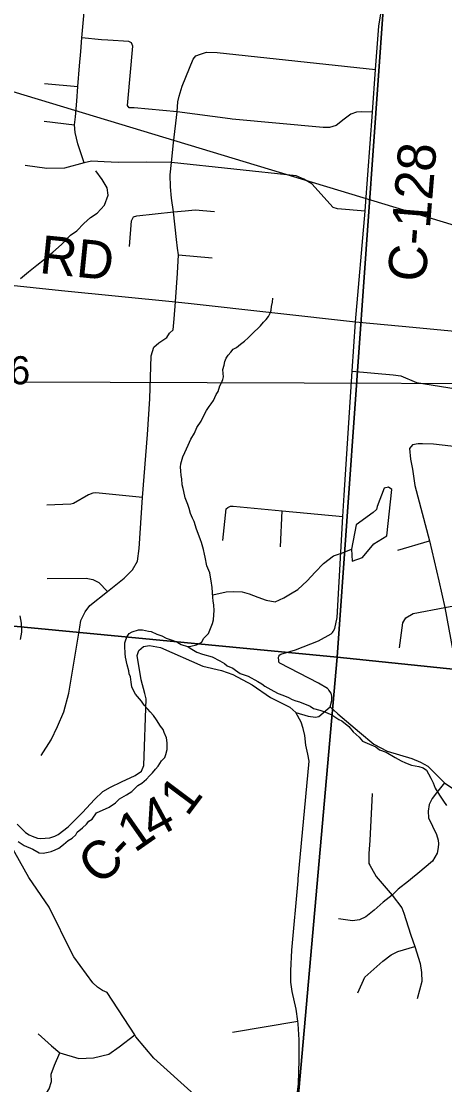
# Model space of a CAD drawing. Extents: x 0 to 43.4, y -8.1 to 22.
# Drawn here: x 5.419 to 6.05, y 17.842 to 19.427 of the extents above; entities that cross this region are included whole.
import ezdxf

# ---------------------------------------------------------------- set-up
doc = ezdxf.new("R2010")
doc.units = 0
for name, color, linetype in [('GM_X_Corporation', 7, 'Continuous'), ('GM_X_County_Road', 7, 'Continuous'), ('GM_X_County_Road_Text', 7, 'Continuous'), ('GM_X_Minor_Lake', 7, 'Continuous'), ('GM_X_Minor_River', 7, 'Continuous'), ('GM_X_Section_Text', 7, 'Continuous'), ('GM_X_Township_Road', 7, 'Continuous'), ('SH_Text', 7, 'Continuous')]:
    doc.layers.add(name, color=color, linetype=linetype)

msp = doc.modelspace()

# ---------------------------------------------------------------- linework, layer by layer
at = {"layer": 'GM_X_Corporation'}
for points in [[(5.9616, 19.4927), (5.8893, 18.4791), (4.8473, 18.579), (4.9462, 19.5972)], [(5.9616, 19.4927), (6.9413, 19.3833), (6.8431, 18.3799), (5.8893, 18.4791)], [(4.8473, 18.579), (5.8893, 18.4791), (5.7989, 17.456), (4.7377, 17.6242)], [(6.8431, 18.3799), (6.7271, 17.3517), (5.7989, 17.456), (5.8893, 18.4791)]]:
    msp.add_lwpolyline(points, close=True, dxfattribs=at)
at = {"layer": 'GM_X_County_Road'}
for p, q in [((5.9168, 18.9788), (5.9863, 18.9721)), ((5.9863, 18.9721), (6.2648, 18.9452))]:
    msp.add_line(p, q, dxfattribs=at)
for points in [[(5.9168, 18.9788), (5.9313, 19.1438), (5.9319, 19.1508), (5.942, 19.2909), (5.9466, 19.3546), (5.9513, 19.4191), (5.9555, 19.4438), (5.9566, 19.4892), (5.9673, 19.632), (5.979, 19.7684), (6.0003, 19.9928)], [(4.8872, 19.0868), (4.9964, 19.0755), (5.1827, 19.0567), (5.4785, 19.0255), (5.6484, 19.0084), (5.672, 19.006), (5.9168, 18.9788)], [(5.8839, 18.5182), (5.8859, 18.5217), (5.8895, 18.5379), (5.8981, 18.6884), (5.9, 18.7206), (5.912, 18.9052), (5.9168, 18.9788)], [(5.8029, 18.4807), (5.8032, 18.4817), (5.8054, 18.4832), (5.8273, 18.4901), (5.8618, 18.5034), (5.8807, 18.5135), (5.8824, 18.5155), (5.8834, 18.5173), (5.8839, 18.5182)], [(5.4127, 18.2303), (5.4249, 18.2175), (5.4307, 18.214), (5.435, 18.212), (5.4428, 18.2091), (5.4473, 18.2086), (5.4613, 18.2098), (5.4688, 18.2123), (5.4736, 18.2147), (5.4888, 18.226), (5.5099, 18.2473), (5.528, 18.2669), (5.5402, 18.279), (5.5518, 18.2851), (5.5683, 18.2933), (5.5883, 18.3025), (5.598, 18.3091), (5.6013, 18.3173), (5.605, 18.4167), (5.6026, 18.4248), (5.5975, 18.4451), (5.5912, 18.4814), (5.5941, 18.4889), (5.6007, 18.4947), (5.6098, 18.4963), (5.6264, 18.4932), (5.6892, 18.4657), (5.7171, 18.4591), (5.7339, 18.4532), (5.7626, 18.4375), (5.79, 18.4188), (5.8188, 18.4045), (5.828, 18.3963)], [(5.879, 18.4051), (5.8817, 18.4144), (5.8815, 18.4206), (5.8803, 18.4254), (5.8772, 18.43), (5.8767, 18.4307), (5.8752, 18.4322), (5.8616, 18.4404), (5.8042, 18.47), (5.8026, 18.4715), (5.8024, 18.4734), (5.8022, 18.4788), (5.8026, 18.4797), (5.8029, 18.4807)], [(5.828, 18.3963), (5.846, 18.3911), (5.857, 18.3896), (5.862, 18.3907), (5.879, 18.4051)], [(5.879, 18.4051), (5.8905, 18.3946), (5.9226, 18.367), (5.9442, 18.3493), (5.9637, 18.3387), (6.0009, 18.3279), (6.0136, 18.3227), (6.0245, 18.3163), (6.036, 18.305), (6.0493, 18.2915), (6.0768, 18.2732), (6.0947, 18.2642), (6.1384, 18.2479), (6.1507, 18.2449), (6.1624, 18.2455), (6.1754, 18.2495), (6.1913, 18.2615), (6.2051, 18.2755), (6.2269, 18.3063), (6.2439, 18.3223), (6.2453, 18.3236), (6.2495, 18.3271)], [(5.8315, 18.1487), (5.8476, 18.3242), (5.8457, 18.3345), (5.8427, 18.3476), (5.8413, 18.362), (5.839, 18.3727), (5.8359, 18.382), (5.828, 18.3963)], [(5.4947, 18.0367), (5.4604, 18.1066), (5.4302, 18.1506), (5.3905, 18.2206)], [(5.7951, 17.4607), (5.8068, 17.5856), (5.8243, 17.7859), (5.8319, 17.8427), (5.8327, 17.8791), (5.8329, 17.9087), (5.8314, 17.9327), (5.8309, 17.9364), (5.8283, 17.9545), (5.8224, 17.9809), (5.8205, 17.9946), (5.8203, 18.0113), (5.8217, 18.0424), (5.8312, 18.1458), (5.8315, 18.1487)], [(5.8243, 17.7859), (5.734, 17.7824), (5.7265, 17.7845), (5.7175, 17.7897), (5.6762, 17.8272), (5.6163, 17.8815), (5.5896, 17.9131), (5.5878, 17.916), (5.5467, 17.9791), (5.5399, 17.982), (5.5322, 17.9872), (5.5252, 17.9938), (5.4969, 18.0324), (5.4947, 18.0367)]]:
    msp.add_lwpolyline(points, dxfattribs=at)
at = {"layer": 'GM_X_Minor_Lake'}
for points in [[(5.9274, 18.6274), (5.9439, 18.6479), (5.9636, 18.6596), (5.9711, 18.7289), (5.9659, 18.7325), (5.9594, 18.7307), (5.9492, 18.7036), (5.9479, 18.6991), (5.9432, 18.6947), (5.9176, 18.676), (5.9106, 18.6399)], [(5.9106, 18.6399), (5.9117, 18.6222), (5.9274, 18.6274)]]:
    msp.add_lwpolyline(points, dxfattribs=at)
at = {"layer": 'GM_X_Minor_River'}
for points in [[(5.4175, 19.0433), (5.4295, 19.0533), (5.442, 19.0632), (5.4533, 19.0723), (5.4657, 19.0823), (5.4786, 19.0941), (5.4919, 19.1077), (5.5016, 19.1143), (5.5121, 19.125), (5.5219, 19.1343), (5.5316, 19.1408), (5.5429, 19.1527), (5.5483, 19.1673), (5.5467, 19.1784), (5.5395, 19.1908), (5.5296, 19.2036)], [(5.6667, 18.7067), (5.6629, 18.7163), (5.6609, 18.7259), (5.6599, 18.7305), (5.6586, 18.7358), (5.6578, 18.7446), (5.6568, 18.7496), (5.6563, 18.7564), (5.6561, 18.7622), (5.6566, 18.7671), (5.6597, 18.7776), (5.6622, 18.784), (5.6675, 18.7948), (5.6712, 18.8038), (5.6768, 18.8127), (5.6805, 18.8214), (5.6869, 18.8306), (5.6906, 18.8393), (5.6947, 18.8463), (5.6987, 18.8523), (5.7019, 18.8567), (5.7051, 18.8616), (5.7092, 18.8705), (5.712, 18.875), (5.7146, 18.8833), (5.717, 18.8878), (5.7191, 18.8926), (5.72, 18.8968), (5.7194, 18.9017), (5.7192, 18.9078), (5.721, 18.9142), (5.7219, 18.9195), (5.724, 18.9244), (5.7268, 18.9292), (5.7311, 18.9333), (5.7347, 18.9377), (5.7393, 18.9406), (5.7452, 18.9453), (5.7514, 18.9497), (5.7569, 18.9548), (5.762, 18.9599), (5.7663, 18.9643), (5.7714, 18.9687), (5.7754, 18.9728), (5.7797, 18.978), (5.7837, 18.982), (5.7869, 18.9864), (5.7897, 18.9917), (5.791, 18.9962), (5.7915, 19.0015), (5.7929, 19.0079), (5.7935, 19.014)], [(5.4586, 18.1882), (5.4632, 18.1892), (5.4693, 18.1916), (5.4747, 18.1945), (5.4818, 18.1999), (5.4888, 18.2058), (5.4946, 18.2094), (5.5001, 18.2141), (5.5021, 18.2182), (5.51, 18.2248), (5.5158, 18.2303), (5.5194, 18.2344), (5.5244, 18.2376), (5.5308, 18.2469), (5.5497, 18.2553), (5.5591, 18.2619), (5.565, 18.2677), (5.5754, 18.2738), (5.5836, 18.2789), (5.5879, 18.2833), (5.5926, 18.2877), (5.5984, 18.2913), (5.6055, 18.2971), (5.6098, 18.3019), (5.6145, 18.3067), (5.6185, 18.3119), (5.6228, 18.3163), (5.6277, 18.3245), (5.6324, 18.3293), (5.6341, 18.3341), (5.6359, 18.3413), (5.6362, 18.3512), (5.6353, 18.3588), (5.6318, 18.3665), (5.63, 18.3712), (5.626, 18.3762), (5.6203, 18.3856), (5.6156, 18.3918), (5.6108, 18.3973), (5.6072, 18.4016), (5.6017, 18.4075), (5.5981, 18.4133), (5.589, 18.4239), (5.5865, 18.4285), (5.5836, 18.4347), (5.5824, 18.4416), (5.5815, 18.4496), (5.5794, 18.4539), (5.5792, 18.4588), (5.5764, 18.4677), (5.5742, 18.4791), (5.5736, 18.4845), (5.5732, 18.4951), (5.573, 18.5001), (5.5743, 18.5046), (5.5764, 18.5095), (5.5796, 18.5143), (5.5842, 18.5168), (5.5934, 18.5199), (5.5995, 18.5197), (5.6082, 18.5179), (5.6123, 18.5174), (5.6209, 18.5133), (5.628, 18.5107), (5.6344, 18.5075), (5.6434, 18.5045), (5.6475, 18.5028), (5.652, 18.5008), (5.6568, 18.4979), (5.6662, 18.4946), (5.6716, 18.4955), (5.68, 18.4971), (5.6877, 18.5011), (5.6902, 18.5067), (5.6976, 18.514), (5.7018, 18.5241), (5.7038, 18.529), (5.7052, 18.5347), (5.7058, 18.5422), (5.706, 18.5487), (5.7055, 18.5563), (5.7046, 18.5628), (5.7044, 18.5678), (5.7039, 18.5754), (5.7031, 18.583), (5.7015, 18.5929), (5.7009, 18.5983), (5.6996, 18.6044), (5.6954, 18.6152), (5.6928, 18.6282), (5.6915, 18.6324), (5.6902, 18.6393), (5.6871, 18.6497), (5.6858, 18.6539), (5.684, 18.6593), (5.6799, 18.6697), (5.6761, 18.6809), (5.674, 18.6863), (5.6708, 18.6932), (5.6688, 18.7005), (5.6667, 18.7067)], [(5.7041, 18.572), (5.7241, 18.5761), (5.7352, 18.5769), (5.7477, 18.5761), (5.7582, 18.5732), (5.7714, 18.5686), (5.7838, 18.5641), (5.797, 18.5614), (5.8101, 18.5675), (5.8198, 18.5733), (5.8306, 18.5799), (5.8447, 18.5928), (5.8568, 18.6057), (5.8689, 18.6183), (5.8841, 18.63), (5.8975, 18.6346), (5.9106, 18.6399)], [(5.4175, 18.5054), (5.4193, 18.5163), (5.419, 18.5296), (5.417, 18.5407)], [(5.667, 18.4947), (5.6703, 18.4925), (5.6804, 18.4865), (5.689, 18.4832), (5.7033, 18.4792), (5.7145, 18.4735), (5.7215, 18.4695), (5.7256, 18.4659), (5.7338, 18.4626), (5.7379, 18.4594), (5.7449, 18.4546), (5.7569, 18.4504), (5.7711, 18.4427), (5.7774, 18.439), (5.7815, 18.4359), (5.7949, 18.4285), (5.8016, 18.4249), (5.8087, 18.4224), (5.817, 18.4187), (5.8222, 18.4158), (5.8278, 18.4137), (5.8331, 18.4124), (5.8492, 18.4061), (5.854, 18.4026), (5.8638, 18.3999), (5.8698, 18.3982), (5.8814, 18.3929), (5.8918, 18.386), (5.8963, 18.384), (5.907, 18.3756), (5.9135, 18.3678), (5.922, 18.3599), (5.9271, 18.3536), (5.9376, 18.3495), (5.9469, 18.3454), (5.9525, 18.341), (5.9626, 18.3376), (5.976, 18.3295), (5.9805, 18.3271), (5.9846, 18.3247), (5.9913, 18.3214), (6.0003, 18.318), (6.0112, 18.3158), (6.0176, 18.314), (6.0224, 18.3104), (6.0257, 18.305), (6.0288, 18.2984), (6.0324, 18.2915), (6.0355, 18.2838), (6.042, 18.2733), (6.0478, 18.2643), (6.0525, 18.2581)], [(5.4139, 18.2042), (5.4232, 18.1985), (5.436, 18.1928), (5.4456, 18.1875), (5.4513, 18.1869), (5.4586, 18.1882)]]:
    msp.add_lwpolyline(points, dxfattribs=at)
at = {"layer": 'GM_X_Township_Road'}
for p, q in [((5.5381, 19.3991), (5.509, 19.4017)), ((5.4534, 19.334), (5.5028, 19.3295)), ((5.4528, 19.2777), (5.4981, 19.2723)), ((5.6529, 19.0787), (5.7034, 19.0741)), ((5.805, 18.6432), (5.8075, 18.697)), ((5.9796, 18.6383), (6.0271, 18.6522)), ((5.7336, 17.9203), (5.8309, 17.9364))]:
    msp.add_line(p, q, dxfattribs=at)
for points in [[(5.5057, 19.3601), (5.5077, 19.3816), (5.509, 19.4017), (5.5137, 19.4564), (5.5175, 19.4906), (5.5167, 19.5074), (5.5154, 19.5189), (5.5112, 19.5354)], [(5.7301, 19.281), (5.6509, 19.2915), (5.5871, 19.2977), (5.5794, 19.2977), (5.5768, 19.3009), (5.5776, 19.3067), (5.5851, 19.3895), (5.5831, 19.3945), (5.5791, 19.3962), (5.5478, 19.3982), (5.5381, 19.3991)], [(5.6509, 19.2915), (5.6518, 19.3066), (5.6539, 19.315), (5.6587, 19.3297), (5.6748, 19.3702), (5.6788, 19.375), (5.6857, 19.3775), (5.6945, 19.3806), (5.7104, 19.3801), (5.9466, 19.3546)], [(5.5125, 19.2156), (5.5032, 19.2438), (5.499, 19.2609), (5.4981, 19.2723), (5.4996, 19.2843), (5.5017, 19.3075), (5.5028, 19.3295), (5.5057, 19.3601)], [(5.4483, 18.3325), (5.4635, 18.3556), (5.4725, 18.3755), (5.4821, 18.3974), (5.4894, 18.4252), (5.5061, 18.5239), (5.5075, 18.5334), (5.5139, 18.5465), (5.521, 18.556), (5.547, 18.5769), (5.5722, 18.5967), (5.5847, 18.6093), (5.5919, 18.6221), (5.5943, 18.6407), (5.5995, 18.717), (5.6067, 18.8106), (5.6105, 18.8641), (5.6122, 18.9282), (5.616, 18.941), (5.6238, 18.9472), (5.6355, 18.9555), (5.6398, 18.9619), (5.6451, 18.9668), (5.6466, 18.9833), (5.6484, 19.0084), (5.6517, 19.0512), (5.6529, 19.0787), (5.6514, 19.0884), (5.6502, 19.1013), (5.6456, 19.1428), (5.6428, 19.1629), (5.6413, 19.1798), (5.6404, 19.1979), (5.6425, 19.2162), (5.6455, 19.2456), (5.6509, 19.2915)], [(5.942, 19.2909), (5.9261, 19.2918), (5.918, 19.2912), (5.9099, 19.2879), (5.8998, 19.2807), (5.8881, 19.2713), (5.8781, 19.2683), (5.8686, 19.2683), (5.7331, 19.2806), (5.7301, 19.281)], [(5.5421, 19.217), (5.5233, 19.218), (5.5125, 19.2156), (5.4831, 19.2075), (5.457, 19.2072), (5.4247, 19.2115)], [(5.9313, 19.1438), (5.8901, 19.1472), (5.8837, 19.1489), (5.8519, 19.1845), (5.8399, 19.1914), (5.8285, 19.1962), (5.6425, 19.2162), (5.6057, 19.2167), (5.5629, 19.2159), (5.5421, 19.217)], [(5.5798, 19.0911), (5.5832, 19.1292), (5.5858, 19.1353), (5.591, 19.1366), (5.6456, 19.1428), (5.6628, 19.1443), (5.6776, 19.1458), (5.7068, 19.1432)], [(5.912, 18.9052), (5.973, 18.8999), (5.9843, 18.898), (6.0075, 18.8881), (6.0916, 18.8748), (6.1165, 18.8706), (6.1266, 18.8683), (6.1348, 18.8639), (6.1403, 18.8569), (6.1585, 18.7993), (6.1609, 18.7918), (6.1681, 18.769), (6.1714, 18.7643), (6.1765, 18.7592), (6.2206, 18.7407)], [(6.104, 18.7882), (6.1021, 18.7884), (6.0844, 18.7904), (6.0329, 18.7966), (6.0168, 18.797), (6.0099, 18.7967), (6.0019, 18.7952), (5.9971, 18.7897)], [(5.9971, 18.7897), (5.9988, 18.7742), (6.0016, 18.7591), (6.0053, 18.7349), (6.0271, 18.6522), (6.0409, 18.5925)], [(5.5995, 18.717), (5.5297, 18.7238), (5.5251, 18.7232), (5.519, 18.7211), (5.4966, 18.7078), (5.4924, 18.7068), (5.4567, 18.7053)], [(5.7192, 18.6528), (5.7242, 18.7001), (5.7265, 18.7019), (5.7304, 18.7041), (5.7335, 18.704), (5.7345, 18.7039), (5.8075, 18.697), (5.8981, 18.6884)], [(5.4573, 18.5962), (5.5154, 18.5966), (5.5255, 18.5945), (5.5343, 18.5903), (5.547, 18.5769)], [(6.0409, 18.5925), (6.0501, 18.5528), (6.0618, 18.4886), (6.0696, 18.4687), (6.0813, 18.4569), (6.1116, 18.4211), (6.1537, 18.3796)], [(5.9825, 18.4927), (5.9874, 18.53), (5.9918, 18.5378), (6.0025, 18.5441), (6.0501, 18.5528), (6.0908, 18.5604), (6.1019, 18.5606), (6.1118, 18.5584), (6.1221, 18.5505), (6.1398, 18.5276)], [(6.0493, 18.2915), (6.0373, 18.2766), (6.0308, 18.2684), (6.0266, 18.2595), (6.0248, 18.2496), (6.0256, 18.2395), (6.0373, 18.2147), (6.0401, 18.2061), (6.0402, 18.2008), (6.0397, 18.1952), (6.0384, 18.187), (6.0315, 18.1747), (6.0096, 18.1568), (6.0015, 18.1501)], [(5.9416, 18.276), (5.938, 18.2058), (5.9368, 18.1866), (5.9367, 18.1717), (5.938, 18.1692), (5.9405, 18.1647)], [(5.9405, 18.1647), (5.9474, 18.1523), (5.9716, 18.1243), (5.9859, 18.1054), (5.9887, 18.0974), (5.9916, 18.0881)], [(6.0015, 18.1501), (5.9956, 18.1452), (5.9802, 18.133), (5.9716, 18.1243), (5.9581, 18.1136), (5.9446, 18.1019), (5.9321, 18.0919), (5.9226, 18.0876), (5.9122, 18.0862), (5.8915, 18.0888)], [(5.9916, 18.0881), (5.9992, 18.0645), (6.0053, 18.0479), (6.0132, 18.0223), (6.0153, 18.0092), (6.0156, 17.9954), (6.0087, 17.9699)], [(5.92, 17.9787), (5.9305, 18.0022), (5.9573, 18.0261), (5.97, 18.0355), (5.9799, 18.0405), (6.0053, 18.0479)], [(5.444, 17.9174), (5.464, 17.8995), (5.4764, 17.8891), (5.5047, 17.8808), (5.5265, 17.8819), (5.5493, 17.8874), (5.5645, 17.8981), (5.5878, 17.916)], [(5.4288, 17.7956), (5.4367, 17.8056), (5.4443, 17.8149), (5.4533, 17.8246), (5.4603, 17.8356), (5.464, 17.8466), (5.4633, 17.8577), (5.4682, 17.8708), (5.4764, 17.8891)]]:
    msp.add_lwpolyline(points, dxfattribs=at)
at = {"layer": 'SH_Text'}
msp.add_lwpolyline([(5.117, 19.4094), (6.8528, 18.8836), (5.117, 18.89)], close=True, dxfattribs=at)

# ---------------------------------------------------------------- texts
at = {"layer": 'GM_X_County_Road_Text'}
for s, height, rotation, p in [('C-128', 0.05682, 85.3275, (6.021, 19.0369)), ('RD', 0.05682, 354.1938, (5.4445, 19.0515)), ('1', 0.0568, 53.1852, (5.6659, 18.2399)), ('4', 0.0568, 28.3725, (5.6149, 18.2059)), ('1', 0.0568, 34.9552, (5.5877, 18.1867)), ('C', 0.0568, 41.3144, (5.5348, 18.137)), ('-', 0.0568, 46.584, (5.574, 18.1718))]:
    msp.add_text(s, height=height, rotation=rotation, dxfattribs=at).set_placement(p)
at = {"layer": 'GM_X_Section_Text'}
msp.add_text('26', height=0.04186, rotation=0, dxfattribs=at).set_placement((5.3698, 18.8856))

doc.saveas('drawing.dxf')
